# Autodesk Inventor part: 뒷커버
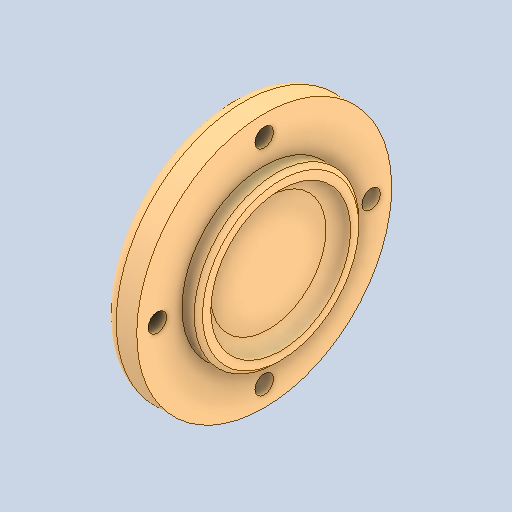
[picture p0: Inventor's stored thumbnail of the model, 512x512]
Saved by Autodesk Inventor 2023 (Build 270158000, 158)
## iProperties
Created: 2024-09
Part Number: 뒷커버
Material: 알루미늄 6061
Document SubType Name: Modeling
Designer: asung
Density: 2.7 g/cm^3
Appearance: 기본값
Author: jhkim
Sending System: Autodesk Inventor 2025
Preprocessor: ST-DEVELOPER v20
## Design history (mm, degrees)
feature "솔리드1"
node "솔리드2"
